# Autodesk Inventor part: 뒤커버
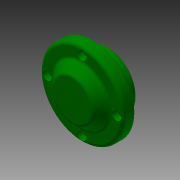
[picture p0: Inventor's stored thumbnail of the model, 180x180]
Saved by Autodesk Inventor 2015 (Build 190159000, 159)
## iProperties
Created: 2017-08
Part Number: 뒤커버
Material: 알루미늄 6061
Document SubType Name: Modeling
Designer: mduedu
Density: 2.71 g/cm^3
Appearance: 알루미늄 - 평지
Author: mduedu
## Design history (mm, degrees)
sketch "스케치1"
  geometry: C1 r 35 at (0, 0); 1 further point
  constraints: 1 centre point, 1 coincident
  dimensions: "d0" = 70 diameter of C1
extrude "돌출1" new body sketch "스케치1" distance "d1" = 10; taper "d2" = 0 deg
sketch "스케치2"
  geometry: C1 r 24 at (0, 0); 1 further point
  constraints: 1 centre point, 1 coincident
  dimensions: "d3" = 48 diameter of C1
node "작업 평면1"
sketch "스케치3"
  geometry: C1 r 17 at (0, 0); 1 further point
  constraints: 1 centre point, 1 coincident
  dimensions: "d5" = 34 diameter of C1
feature "로프트1" sketch "스케치3" dims "d6" = 0, "d7" = 90 deg, "d8" = 0, "d9" = 90 deg
sketch "스케치4"
  geometry: C1 r 24 at (0, 0) reference; 1 further point
extrude "돌출2" join sketch "스케치4" distance "d10" = 12; taper "d11" = 0 deg
hole "구멍1" diameter "d14" = 40; stored, may be unused: countersink angle "d18" = 90 deg, drill point angle "d20" = 0 deg; dims "d15" = 6, "d16" = 4, "d17" = 2, "d19" = 12, "d64" = 10, "d65" = 10
hole "구멍2" diameter "d23" = 36; stored, may be unused: countersink angle "d27" = 90 deg, drill point angle "d29" = 0 deg; dims "d24" = 6, "d25" = 4, "d26" = 2, "d28" = 8, "d62" = 10, "d63" = 10
chamfer "모따기1" distance "d39" = 1; stored, may be unused: second distance "d40" = 2, angle "d41" = 45 deg
fillet "모깎기1" dims "d42" = 0.3
fillet "모깎기2" dims "d43" = 3
sketch "스케치5" dims "d44" = 58
  geometry: 6 further points
  constraints: 2 vertical alignment, 1 coincident, 7 other
  dimensions: "d47" = 360 deg dimension on point (0, 0) point (0, 29) (derived)
sketch "스케치6"
  geometry: 4 further points
  constraints: 4 other
hole "구멍4" sketch "스케치6" at (0, 29), (-29, 0), (29, 0), (0, -29) diameter "d49" = 4.5; stored, may be unused: countersink angle "d53" = 90 deg, drill point angle "d55" = 0 deg; dims "d50" = 6, "d51" = 8, "d52" = 4.6, "d54" = 8
fillet "모깎기3" dims "d56" = 3
fillet "모깎기4" dims "d57" = 3
fillet "모깎기5" dims "d58" = 3
chamfer "모따기2" distance "d59" = 1; stored, may be unused: second distance "d60" = 2, angle "d61" = 45 deg
node "솔리드1"
other parameters: "d4" = 8
